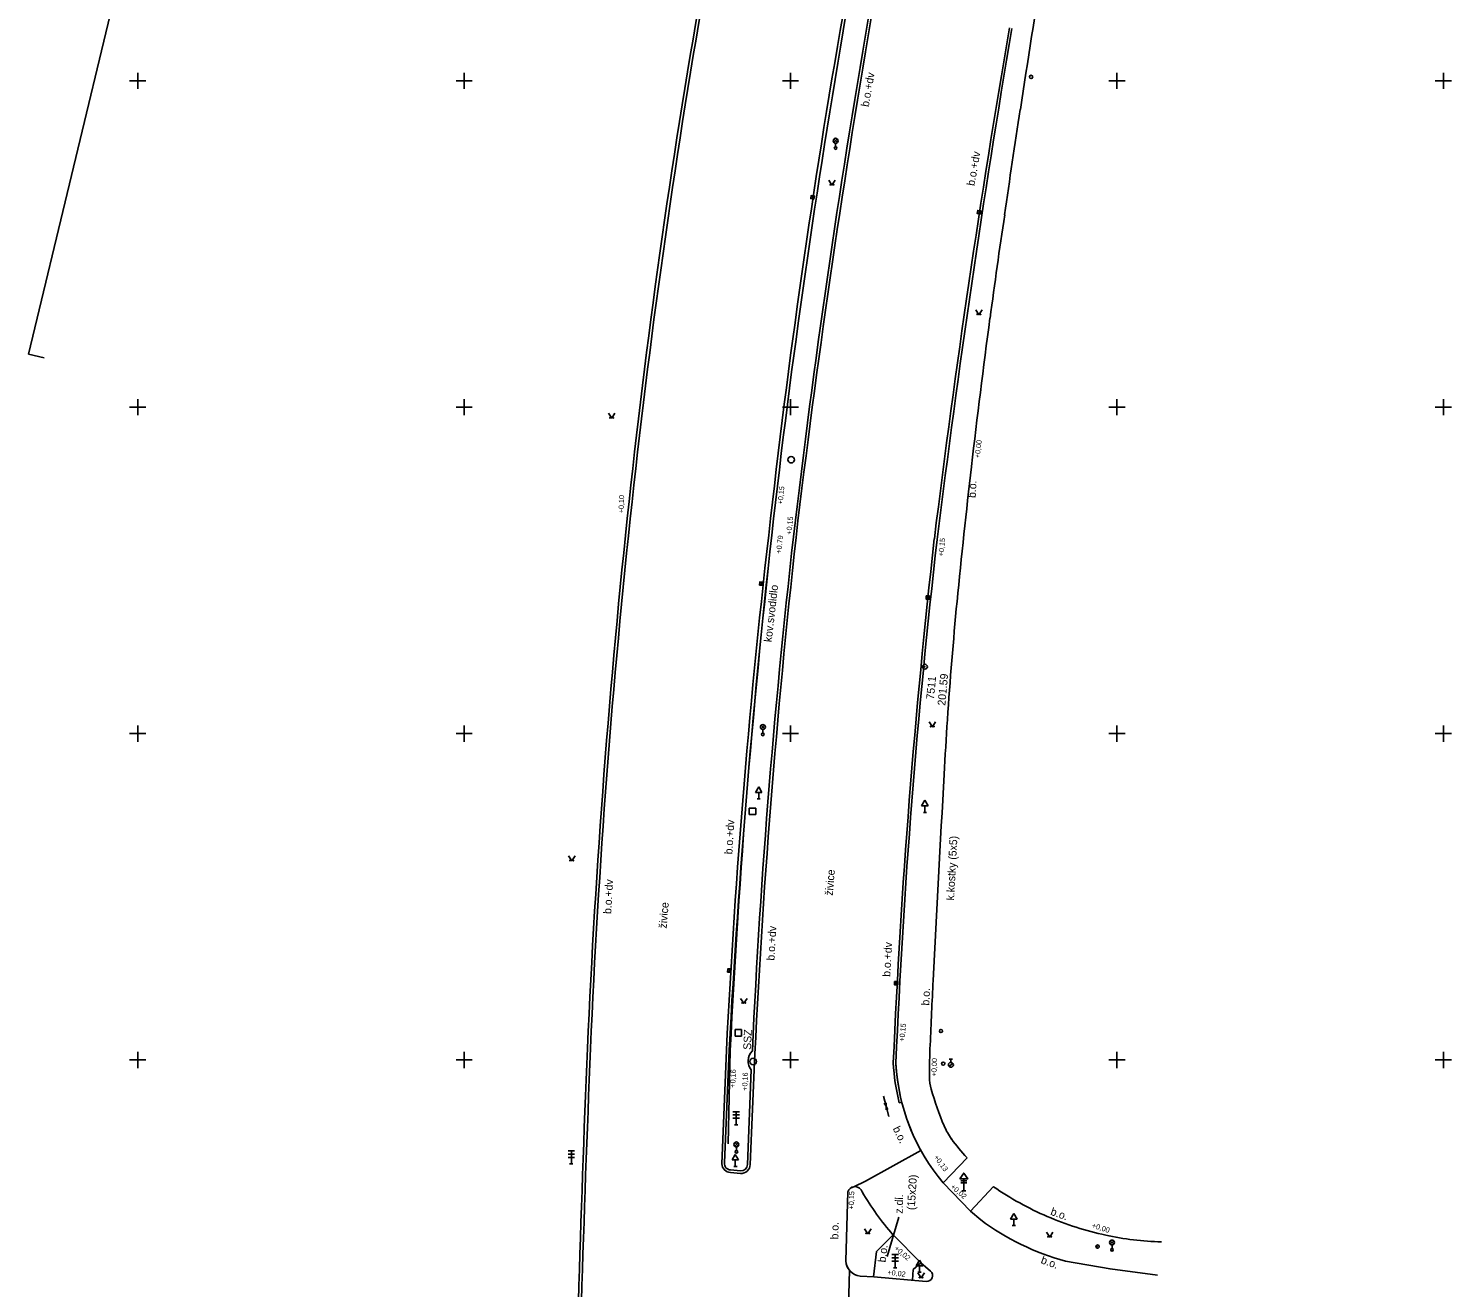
# Model space of a CAD drawing. Extents: x -599151 to -598424, y -1163476 to -1161924.
# Drawn here: x -598708.4 to -598599.4, y -1162392.4 to -1162296 of the extents above; entities that cross this region are included whole.
import ezdxf

# ---------------------------------------------------------------- set-up
doc = ezdxf.new("R2010")
doc.units = 0
for name, color, linetype in [('Vrstva 1', 7, 'Continuous'), ('Vrstva 14', 7, 'Continuous'), ('Vrstva 15', 7, 'Continuous'), ('Vrstva 19', 7, 'Continuous'), ('Vrstva 2', 7, 'Continuous'), ('Vrstva 21', 7, 'Continuous'), ('Vrstva 23', 7, 'Continuous'), ('Vrstva 24', 7, 'Continuous'), ('Vrstva 25', 7, 'Continuous'), ('Vrstva 29', 7, 'Continuous'), ('Vrstva 44', 7, 'Continuous'), ('Vrstva 49', 7, 'Continuous'), ('Vrstva 50', 7, 'Continuous'), ('Vrstva 62', 7, 'Continuous'), ('Vrstva 63', 7, 'Continuous'), ('Vrstva 7', 7, 'Continuous')]:
    doc.layers.add(name, color=color, linetype=linetype)

msp = doc.modelspace()

# ---------------------------------------------------------------- linework, layer by layer
at = {"layer": 'Vrstva 1'}
for p in [(-598622.44, -1161963.62), (-598707.16, -1162321.22)]:
    msp.add_line(p, (-598708.37, -1162320.93), dxfattribs=at)
at = {"layer": 'Vrstva 14'}
for points in [[(-598647.08, -1162307.61), (-598646.83, -1162307.99), (-598646.58, -1162307.61)], [(-598635.82, -1162317.54), (-598635.57, -1162317.92), (-598635.32, -1162317.54)], [(-598663.95, -1162325.46), (-598663.7, -1162325.83), (-598663.45, -1162325.46)], [(-598639.39, -1162349.11), (-598639.14, -1162349.49), (-598638.89, -1162349.11)], [(-598667.01, -1162359.37), (-598666.76, -1162359.74), (-598666.51, -1162359.37)], [(-598653.83, -1162370.28), (-598653.58, -1162370.65), (-598653.33, -1162370.28)], [(-598644.33, -1162387.94), (-598644.08, -1162388.31), (-598643.83, -1162387.94)], [(-598630.4, -1162388.19), (-598630.15, -1162388.56), (-598629.9, -1162388.19)], [(-598640.25, -1162391.31), (-598640, -1162391.69), (-598639.75, -1162391.31)]]:
    msp.add_lwpolyline(points, dxfattribs=at)
for centre in [(-598646.95, -1162307.96), (-598646.7, -1162307.96), (-598635.7, -1162317.89), (-598635.45, -1162317.89), (-598663.83, -1162325.81), (-598663.58, -1162325.81), (-598639.27, -1162349.46), (-598639.02, -1162349.46), (-598666.89, -1162359.72), (-598666.64, -1162359.72), (-598653.71, -1162370.63), (-598653.46, -1162370.63), (-598644.21, -1162388.28), (-598643.96, -1162388.28), (-598630.28, -1162388.54), (-598630.03, -1162388.54), (-598640.13, -1162391.66), (-598639.88, -1162391.66)]:
    msp.add_circle(centre, 0.025, dxfattribs=at)
at = {"layer": 'Vrstva 15'}
for radius in [0.125, 0.00025]:
    msp.add_circle((-598626.49, -1162389.29), radius, dxfattribs=at)
at = {"layer": 'Vrstva 19'}
for p, q in [((-598652.44, -1162354.07), (-598652.69, -1162354.5)), ((-598652.44, -1162354.07), (-598652.19, -1162354.5)), ((-598652.69, -1162354.5), (-598652.19, -1162354.5)), ((-598652.57, -1162355), (-598652.32, -1162355)), ((-598652.44, -1162355), (-598652.44, -1162354.5)), ((-598639.71, -1162355.11), (-598639.96, -1162355.54)), ((-598639.71, -1162355.11), (-598639.46, -1162355.54)), ((-598639.96, -1162355.54), (-598639.46, -1162355.54)), ((-598639.83, -1162356.04), (-598639.58, -1162356.04)), ((-598639.71, -1162356.04), (-598639.71, -1162355.54)), ((-598653.91, -1162378.96), (-598654.41, -1162378.96)), ((-598654.41, -1162379.21), (-598653.91, -1162379.21)), ((-598654.16, -1162379.96), (-598654.16, -1162378.96)), ((-598654.41, -1162379.46), (-598653.91, -1162379.46)), ((-598654.29, -1162379.96), (-598654.04, -1162379.96)), ((-598666.54, -1162381.96), (-598667.04, -1162381.96)), ((-598667.04, -1162382.21), (-598666.54, -1162382.21)), ((-598667.04, -1162382.46), (-598666.54, -1162382.46)), ((-598666.79, -1162382.96), (-598666.79, -1162381.96)), ((-598654.23, -1162382.23), (-598654.48, -1162382.66)), ((-598654.23, -1162382.23), (-598653.98, -1162382.66)), ((-598666.92, -1162382.96), (-598666.67, -1162382.96)), ((-598654.48, -1162382.66), (-598653.98, -1162382.66)), ((-598654.35, -1162383.16), (-598654.1, -1162383.16)), ((-598654.23, -1162383.16), (-598654.23, -1162382.66)), ((-598632.9, -1162386.76), (-598633.15, -1162387.19)), ((-598632.9, -1162386.76), (-598632.65, -1162387.19)), ((-598633.15, -1162387.19), (-598632.65, -1162387.19)), ((-598633.03, -1162387.69), (-598632.78, -1162387.69)), ((-598632.9, -1162387.69), (-598632.9, -1162387.19)), ((-598641.74, -1162389.91), (-598642.24, -1162389.91)), ((-598642.24, -1162390.16), (-598641.74, -1162390.16)), ((-598641.99, -1162390.91), (-598641.99, -1162389.91)), ((-598642.24, -1162390.41), (-598641.74, -1162390.41)), ((-598642.11, -1162390.91), (-598641.86, -1162390.91)), ((-598640.12, -1162390.33), (-598640.37, -1162390.76)), ((-598640.37, -1162390.76), (-598639.87, -1162390.76)), ((-598640.24, -1162391.26), (-598639.99, -1162391.26)), ((-598640.12, -1162390.33), (-598639.87, -1162390.76)), ((-598640.12, -1162391.26), (-598640.12, -1162390.76))]:
    msp.add_line(p, q, dxfattribs=at)
at = {"layer": 'Vrstva 2'}
for radius in [0.187, 0.00896]:
    msp.add_circle((-598639.71, -1162344.88), radius, dxfattribs=at)
at = {"layer": 'Vrstva 21'}
msp.add_lwpolyline([(-598654.62, -1162374.28), (-598654.79, -1162381.41)], dxfattribs=at)
for centre, radius, start, end in [((-597963.69, -1162412.59), 692.14, 170.10853, 173.4421), ((-598042.83, -1162403.63), 612.49, 173.42894, 177.25331)]:
    msp.add_arc(centre, radius, start, end, dxfattribs=at)
at = {"layer": 'Vrstva 23'}
for p, q in [((-598652.67, -1162355.7), (-598653.17, -1162355.7)), ((-598653.17, -1162355.7), (-598653.17, -1162356.2)), ((-598653.17, -1162356.2), (-598652.67, -1162356.2)), ((-598652.67, -1162356.2), (-598652.67, -1162355.7)), ((-598653.75, -1162372.67), (-598654.25, -1162372.67)), ((-598654.25, -1162372.67), (-598654.25, -1162373.17)), ((-598653.75, -1162373.17), (-598653.75, -1162372.67)), ((-598654.25, -1162373.17), (-598653.75, -1162373.17))]:
    msp.add_line(p, q, dxfattribs=at)
at = {"layer": 'Vrstva 24'}
for p, q in [((-598637.84, -1162374.93), (-598637.59, -1162374.93)), ((-598637.72, -1162375.18), (-598637.72, -1162374.93)), ((-598637.87, -1162375.49), (-598637.57, -1162375.26))]:
    msp.add_line(p, q, dxfattribs=at)
for centre, radius in [((-598631.58, -1162299.7), 0.125), ((-598638.48, -1162372.78), 0.125), ((-598638.31, -1162375.28), 0.125), ((-598637.72, -1162375.37), 0.188)]:
    msp.add_circle(centre, radius, dxfattribs=at)
at = {"layer": 'Vrstva 25'}
for p, q in [((-598648.33, -1162309.04), (-598648.29, -1162308.8)), ((-598635.58, -1162310.19), (-598635.54, -1162309.95)), ((-598652.24, -1162338.64), (-598652.23, -1162338.39)), ((-598639.49, -1162339.71), (-598639.48, -1162339.46)), ((-598654.7, -1162368.28), (-598654.68, -1162368.03)), ((-598641.92, -1162369.25), (-598641.91, -1162369))]:
    msp.add_line(p, q, dxfattribs=at)
for points in [[(-598648.21, -1162309.06), (-598648.17, -1162308.82), (-598648.41, -1162308.78), (-598648.45, -1162309.02)], [(-598635.46, -1162310.21), (-598635.42, -1162309.97), (-598635.66, -1162309.93), (-598635.7, -1162310.17)], [(-598652.12, -1162338.64), (-598652.11, -1162338.39), (-598652.36, -1162338.38), (-598652.37, -1162338.63)], [(-598639.37, -1162339.71), (-598639.36, -1162339.46), (-598639.61, -1162339.45), (-598639.62, -1162339.7)], [(-598654.57, -1162368.28), (-598654.56, -1162368.03), (-598654.81, -1162368.02), (-598654.82, -1162368.27)], [(-598641.79, -1162369.25), (-598641.78, -1162369), (-598642.03, -1162368.99), (-598642.04, -1162369.24)]]:
    msp.add_lwpolyline(points, close=True, dxfattribs=at)
for centre in [(-598649.96, -1162329.02), (-598652.87, -1162375.12)]:
    msp.add_circle(centre, 0.25, dxfattribs=at)
at = {"layer": 'Vrstva 29'}
for p, q in [((-598646.41, -1162304.72), (-598646.68, -1162304.45)), ((-598646.68, -1162304.72), (-598646.42, -1162304.46)), ((-598646.55, -1162305.05), (-598646.55, -1162304.78)), ((-598652.25, -1162349.63), (-598651.99, -1162349.36)), ((-598651.98, -1162349.63), (-598652.25, -1162349.36)), ((-598652.12, -1162349.96), (-598652.12, -1162349.69)), ((-598654.28, -1162381.6), (-598654.02, -1162381.33)), ((-598654.01, -1162381.6), (-598654.28, -1162381.33)), ((-598654.15, -1162381.93), (-598654.15, -1162381.66)), ((-598625.51, -1162389.11), (-598625.25, -1162388.84)), ((-598625.24, -1162389.11), (-598625.51, -1162388.84)), ((-598625.38, -1162389.44), (-598625.38, -1162389.17))]:
    msp.add_line(p, q, dxfattribs=at)
for centre, radius in [((-598646.55, -1162304.59), 0.188), ((-598646.55, -1162305.15), 0.1), ((-598652.12, -1162349.5), 0.188), ((-598652.12, -1162350.06), 0.1), ((-598654.15, -1162381.47), 0.188), ((-598654.15, -1162382.03), 0.1), ((-598625.38, -1162388.98), 0.188), ((-598625.38, -1162389.54), 0.1)]:
    msp.add_circle(centre, radius, dxfattribs=at)
at = {"layer": 'Vrstva 44'}
for p, q in [((-598636.95, -1162384.26), (-598636.5, -1162384.26)), ((-598636.95, -1162384.41), (-598636.51, -1162384.41)), ((-598636.73, -1162384.11), (-598636.73, -1162385.01)), ((-598636.88, -1162385.01), (-598636.58, -1162385.01))]:
    msp.add_line(p, q, dxfattribs=at)
msp.add_lwpolyline([(-598637.03, -1162384.11), (-598636.73, -1162383.66), (-598636.43, -1162384.11)], close=True, dxfattribs=at)
at = {"layer": 'Vrstva 49'}
for p, q in [((-598642.88, -1162377.78), (-598642.68, -1162378.55)), ((-598642.68, -1162378.55), (-598642.82, -1162378.31)), ((-598642.68, -1162378.27), (-598642.68, -1162378.55)), ((-598642.48, -1162379.32), (-598642.68, -1162378.55)), ((-598642.68, -1162378.83), (-598642.68, -1162378.55)), ((-598642.68, -1162378.55), (-598642.55, -1162378.79)), ((-598642.59, -1162390.04), (-598641.72, -1162387.03))]:
    msp.add_line(p, q, dxfattribs=at)
at = {"layer": 'Vrstva 62'}
for p, q in [((-598700, -1162300.62), (-598700, -1162299.38)), ((-598675, -1162300.62), (-598675, -1162299.38)), ((-598650, -1162300.62), (-598650, -1162299.38)), ((-598625, -1162300.62), (-598625, -1162299.38)), ((-598600, -1162300.62), (-598600, -1162299.38)), ((-598700.62, -1162300), (-598699.38, -1162300)), ((-598675.62, -1162300), (-598674.38, -1162300)), ((-598650.62, -1162300), (-598649.38, -1162300)), ((-598625.62, -1162300), (-598624.38, -1162300)), ((-598600.62, -1162300), (-598599.38, -1162300)), ((-598700, -1162325.62), (-598700, -1162324.38)), ((-598675, -1162325.62), (-598675, -1162324.38)), ((-598650, -1162325.62), (-598650, -1162324.38)), ((-598625, -1162325.62), (-598625, -1162324.38)), ((-598600, -1162325.62), (-598600, -1162324.38)), ((-598700.62, -1162325), (-598699.38, -1162325)), ((-598675.62, -1162325), (-598674.38, -1162325)), ((-598650.62, -1162325), (-598649.38, -1162325)), ((-598625.62, -1162325), (-598624.38, -1162325)), ((-598600.62, -1162325), (-598599.38, -1162325)), ((-598700, -1162350.62), (-598700, -1162349.38)), ((-598675, -1162350.62), (-598675, -1162349.38)), ((-598650, -1162350.62), (-598650, -1162349.38)), ((-598625, -1162350.62), (-598625, -1162349.38)), ((-598600, -1162350.62), (-598600, -1162349.38)), ((-598700.62, -1162350), (-598699.38, -1162350)), ((-598675.62, -1162350), (-598674.38, -1162350)), ((-598650.62, -1162350), (-598649.38, -1162350)), ((-598625.62, -1162350), (-598624.38, -1162350)), ((-598600.62, -1162350), (-598599.38, -1162350)), ((-598700, -1162375.62), (-598700, -1162374.38)), ((-598675, -1162375.62), (-598675, -1162374.38)), ((-598650, -1162375.62), (-598650, -1162374.38)), ((-598625, -1162375.62), (-598625, -1162374.38)), ((-598600, -1162375.62), (-598600, -1162374.38)), ((-598700.62, -1162375), (-598699.38, -1162375)), ((-598675.62, -1162375), (-598674.38, -1162375)), ((-598650.62, -1162375), (-598649.38, -1162375)), ((-598625.62, -1162375), (-598624.38, -1162375)), ((-598600.62, -1162375), (-598599.38, -1162375))]:
    msp.add_line(p, q, dxfattribs=at)
at = {"layer": 'Vrstva 63'}
for points in [[(-598655.06, -1162382.88), (-598654.71, -1162374.26)], [(-598653.01, -1162375.76), (-598653.29, -1162383.01)], [(-598645.15, -1162384.71), (-598644.27, -1162384.28), (-598640.02, -1162381.93)], [(-598653.83, -1162383.49), (-598654.6, -1162383.42)], [(-598645.61, -1162385.1), (-598645.77, -1162390.39)], [(-598645.65, -1162396.7), (-598645.48, -1162391.11)]]:
    msp.add_lwpolyline(points, dxfattribs=at)
for centre, radius, start, end in [((-598078.54, -1162394.97), 587.19, 169.87698, 173.86679), ((-597963.69, -1162412.59), 692.14, 170.10853, 173.4421), ((-597911.96, -1162421.25), 742.85, 170.13971, 173.22764), ((-597740.96, -1162446.32), 904.67, 170.43462, 172.94064), ((-597987.91, -1162404.67), 678.34, 173.86948, 177.41683), ((-597942.69, -1162413.38), 713.09, 173.57123, 176.85491), ((-598064.04, -1162401.63), 589.52, 173.37851, 177.34602), ((-598079.18, -1162399.41), 563.27, 173.4486, 177.5421), ((-597162.6, -1162436.92), 1504.27, 177.6066, 179.08394), ((-598652.23, -1162375.09), 1.03, 132.8473, 220.7487), ((-598626.43, -1162374.43), 15.52, 183.0199, 208.8935), ((-598654.58, -1162382.94), 0.481, 172.9795, 267.8727), ((-598653.8, -1162382.98), 0.513, 266.899, 356.368), ((-598645.06, -1162385.28), 0.579, 98.9351, 161.6492), ((-598644.52, -1162390.3), 1.26, 183.929, 219.948)]:
    msp.add_arc(centre, radius, start, end, dxfattribs=at)
at = {"layer": 'Vrstva 7'}
for p, q in [((-598642.15, -1162388.39), (-598640.02, -1162390.54)), ((-598640.02, -1162390.54), (-598639.28, -1162391.18)), ((-598639.61, -1162391.96), (-598643.62, -1162391.61))]:
    msp.add_line(p, q, dxfattribs=at)
for points in [[(-598655.26, -1162382.96), (-598654.91, -1162374.25)], [(-598655.06, -1162382.88), (-598654.71, -1162374.26)], [(-598652.73, -1162374.52), (-598653.09, -1162383.01)], [(-598653.01, -1162375.76), (-598653.29, -1162383.01)], [(-598641.48, -1162378.23), (-598641.67, -1162378.28)], [(-598638.31, -1162384.42), (-598636.48, -1162382.49)], [(-598653.84, -1162383.69), (-598654.61, -1162383.62)], [(-598653.83, -1162383.49), (-598654.6, -1162383.42)], [(-598638.31, -1162384.42), (-598636.23, -1162386.58), (-598635.43, -1162387.25)], [(-598636.23, -1162386.58), (-598634.45, -1162384.7)], [(-598645.61, -1162385.1), (-598645.77, -1162390.39)], [(-598642.15, -1162388.39), (-598643.43, -1162389.68), (-598643.66, -1162391.61)], [(-598640.02, -1162390.54), (-598640.62, -1162391.05), (-598640.66, -1162391.87)], [(-598628.95, -1162390.41), (-598625.53, -1162391), (-598621.89, -1162391.49)], [(-598644.67, -1162391.55), (-598643.62, -1162391.61)]]:
    msp.add_lwpolyline(points, dxfattribs=at)
for centre, radius, start, end in [((-595088.62, -1162847.57), 3585.5, 171.07055, 171.25097), ((-598078.54, -1162394.97), 587.19, 169.87697, 173.86679), ((-598051.2, -1162398.68), 614.54, 169.98126, 173.7942), ((-598011.35, -1162405.68), 644.23, 169.98614, 173.56856), ((-597963.69, -1162412.59), 692.14, 170.10853, 173.4421), ((-597911.96, -1162421.25), 742.85, 170.13971, 173.22764), ((-597873.54, -1162427.08), 781.49, 170.20184, 173.13718), ((-597790.29, -1162439.78), 855.13, 170.31711, 172.96797), ((-597740.96, -1162446.32), 904.67, 170.43462, 172.94064), ((-597938.68, -1162409.87), 702.03, 171.17716, 171.84362), ((-598164.45, -1162380.51), 474.38, 171.4852, 172.4506), ((-597873.28, -1162418.63), 768.05, 172.48488, 173.33967), ((-598187, -1162382.78), 452.28, 173.2418, 174.5593), ((-597987.91, -1162404.67), 678.34, 173.86948, 177.41683), ((-598018.91, -1162402.17), 647.02, 173.79663, 177.51483), ((-598045.5, -1162404.32), 610.15, 173.337, 177.17577), ((-597942.69, -1162413.38), 713.09, 173.57123, 176.85491), ((-598064.04, -1162401.63), 589.52, 173.37851, 177.34602), ((-598007.76, -1162406.12), 645.75, 173.56096, 177.19525), ((-598060.71, -1162400.53), 581.97, 173.5441, 177.50784), ((-598079.18, -1162399.41), 563.27, 173.4486, 177.5421), ((-598300.81, -1162371.79), 337.95, 174.5839, 176.1206), ((-598286.75, -1162372.44), 352.02, 176.1712, 176.8556), ((-596322.1, -1162483.47), 2319.8, 176.77892, 177.16915), ((-598248.9, -1162389.74), 390.73, 176.9433, 177.6678), ((-598560.86, -1162376.93), 78.51, 177.7449, 179.5196), ((-597162.6, -1162436.92), 1504.27, 177.6066, 179.08396), ((-597164.99, -1162437.64), 1501.67, 177.57529, 179.05447), ((-598652.23, -1162375.09), 1.03, 132.8473, 220.7487), ((-598626.43, -1162374.43), 15.72, 182.8723, 194.1648), ((-598626.43, -1162374.43), 15.52, 183.0199, 220.0649), ((-598636.05, -1162376.3), 3.31, 179.5196, 196.6213), ((-598610.26, -1162368.6), 30.23, 196.6213, 202.2587), ((-598633.67, -1162378.18), 4.93, 202.2587, 215.6522), ((-598627.08, -1162373.45), 13.04, 215.6522, 223.876), ((-598654.58, -1162382.94), 0.681, 181.4208, 267.7131), ((-598654.58, -1162382.94), 0.481, 172.9795, 267.8727), ((-598653.8, -1162382.98), 0.713, 267.0191, 357.7883), ((-598653.8, -1162382.98), 0.513, 266.899, 356.368), ((-598645.06, -1162385.28), 0.579, 18.3508, 161.6492), ((-598620.84, -1162364.99), 23.96, 235.3794, 246.6406), ((-598625.67, -1162374.13), 21.8, 210.2171, 220.8582), ((-598620.84, -1162364.99), 23.96, 246.6406, 257.9018), ((-598623.66, -1162371.33), 19.8, 233.5368, 254.5199), ((-598620.84, -1162364.99), 23.96, 257.9018, 263.0406), ((-598620.84, -1162364.99), 23.96, 263.0406, 268.1793), ((-598644.52, -1162390.3), 1.26, 183.929, 263.0295), ((-598639.57, -1162391.52), 0.446, 265.065, 49.6376)]:
    msp.add_arc(centre, radius, start, end, dxfattribs=at)

# ---------------------------------------------------------------- texts
at = {"layer": 'Vrstva 2'}
for s, rotation, p in [('201.59', 84.7088, (-598638.15, -1162347.88)), ('7511', 84.5632, (-598639.02, -1162347.41))]:
    msp.add_text(s, height=0.6, rotation=rotation, dxfattribs=at).set_placement(p)
at = {"layer": 'Vrstva 49'}
for s, rotation, p in [('b.o.+dv', 79.9473, (-598644.02, -1162302.03)), ('b.o.+dv', 79.9473, (-598635.92, -1162308.08)), ('b.o.', 87.2974, (-598635.82, -1162331.96)), ('kov.svodidlo', 83.4613, (-598651.45, -1162343.02)), ('b.o.+dv', 86.669, (-598654.46, -1162359.26)), ('k.kostky (5x5)', 86.9238, (-598637.48, -1162362.79)), ('živice', 85.3272, (-598646.77, -1162362.43)), ('b.o.+dv', 86.669, (-598663.74, -1162363.83)), ('živice', 85.3272, (-598659.49, -1162364.94)), ('b.o.+dv', 86.669, (-598651.24, -1162367.4)), ('b.o.+dv', 86.669, (-598642.37, -1162368.64)), ('b.o.', 87.2974, (-598639.38, -1162370.84)), ('SSZ', 87.5604, (-598653.03, -1162374.23)), ('b.o.', 295.9132, (-598642.19, -1162380.25)), ('(15x20)', 86.3706, (-598640.49, -1162386.51)), ('z.dl.', 88.2257, (-598641.42, -1162386.77)), ('b.o.', 340.0678, (-598630.14, -1162386.84)), ('b.o.', 89.0349, (-598646.34, -1162388.75)), ('b.o.', 83.1304, (-598642.72, -1162390.53)), ('b.o.', 340.0678, (-598630.88, -1162390.55))]:
    msp.add_text(s, height=0.6, rotation=rotation, dxfattribs=at).set_placement(p)
at = {"layer": 'Vrstva 50'}
for s, rotation, p in [('+0,00', 83.1076, (-598635.52, -1162328.92)), ('+0,15', 84.409, (-598650.61, -1162332.46)), ('+0,10', 88.4642, (-598662.78, -1162333.13)), ('+0,15', 84.409, (-598649.94, -1162334.78)), ('+0.79', 83.6425, (-598650.72, -1162336.23)), ('+0,15', 84.409, (-598638.29, -1162336.43)), ('+0,15', 84.409, (-598641.29, -1162373.61)), ('+0,00', 87.7377, (-598638.83, -1162376.26)), ('+0,16', 87.7883, (-598654.24, -1162377.12)), ('+0,16', 87.7883, (-598653.32, -1162377.36)), ('+0,13', 306.0445, (-598639.05, -1162382.45)), ('+0,02', 319.2432, (-598637.78, -1162384.77)), ('+0,15', 88.2676, (-598645.16, -1162386.45)), ('+0,00', 342.2781, (-598626.96, -1162387.83)), ('+0,02', 319.2432, (-598642.09, -1162389.49)), ('+0,02', 352.7262, (-598642.6, -1162391.44))]:
    msp.add_text(s, height=0.4, rotation=rotation, dxfattribs=at).set_placement(p)

doc.saveas('drawing.dxf')
